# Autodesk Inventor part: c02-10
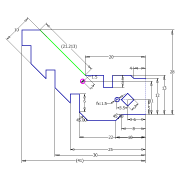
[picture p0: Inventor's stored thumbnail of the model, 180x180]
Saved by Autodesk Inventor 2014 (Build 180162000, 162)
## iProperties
Created: 2013-02
Part Number: c02-10
Material: Generic
Document SubType Name: Modeling
Designer: Thom Tremblay
Density: 1 g/cm^3
Appearance: Default
Author: Thom Tremblay
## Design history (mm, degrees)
sketch "Sketch1"
  geometry: L1 (0, 0)-(-8, 0); L2 (-8, 0)-(-10, -2); L3 (-10, -2)-(-19.142, -2); L4 (-19.142, -2)-(-22, 0.858); L5 (-22, 0.858)-(-22, 6.858); L6 (-22, 6.858)-(-25, 6.858); L7 (-25, 6.858)-(-25, 3.858); L8 (-25, 3.858)-(-30, 8.858); L9 (-30, 8.858)-(-30, 14.858); L10 (-30, 14.858)-(-33, 14.858); L11 (-33, 14.858)-(-33, 11.858); L12 (-33, 11.858)-(-38, 16.858); L13 (-38, 16.858)-(-38, 22.858); L14 (-38, 22.858)-(-41, 22.858); L15 (-41, 22.858)-(-41, 28); L16 (-41, 28)-(-35, 28); L17 (0, 0)-(0, 12); L18 (0, 12)-(-4, 12); L19 (-4, 12)-(-5, 13); L20 (-5, 13)-(-11, 13); L21 (-11, 13)-(-11, 9); L22 (-11, 9)-(-14, 9); L23 (-14, 9)-(-14, 13); L24 (-14, 13)-(-20, 13); L25 (-20, 13)-(-35, 28); L26 (-6, 7.121)-(-3.879, 5); L27 (-3.879, 5)-(-6, 2.879); L28 (-6, 2.879)-(-8.121, 5); L29 (-8.121, 5)-(-6, 7.121); L30 (-6, 5)-(-9.5, 5); C1 r 0.75 at (-20.828, 11); C2 r 0.75 at (-9.5, 5)
  constraints: 60 end point, 17 parallel, 7 equal length, 5 collinear, 4 perpendicular, 2 centre point, 1 coincident, 1 horizontal, 1 vertical alignment, 9 other
  dimensions: "d0" = 8 distance of L1.start L1.end; "d1" = 45 deg angle of L1 L2; "d2" = 45 deg angle of L4 L3; "d3" = 10 distance from line of L2.end L17; "d4" = 12 distance of L1.start L17.end; "d5" = 22 distance between parallel lines of L5 L17; "d6" = 25 distance between parallel lines of L7 L17; "d7" = 6 distance of L4.end L5.end; "d9" = 4 distance of L17.end L18.end; "d10" = 13 distance between parallel lines of L20 L1; "d11" = 10 distance between parallel lines of L12 L25; "d12" = 30 distance between parallel lines of L9 L17; "d14" = 41 distance between parallel lines of L15 L17 (derived); "d15" = 28 distance between parallel lines of L16 L1; "d16" = 20 distance from line of L17 L24.end; "d17" = 4 distance of L20.end L21.end; "d18" = 1.5 diameter of C1; "d19" = 11 distance from line of L1 C1.centre; "d20" = 2 distance from line of L25 C1.centre; "d28" = 3 distance between parallel lines of L26 L28; "d29" = 5 distance from line of L1 L30.start; "d30" = 6 distance from line of L17 L30.start; "d31" = 3.5 distance of L30.start L30.end; "d32" = 1.5 diameter of C2 (= d18); "d33" = 21.2132 distance of L24.end L16.end (derived)
